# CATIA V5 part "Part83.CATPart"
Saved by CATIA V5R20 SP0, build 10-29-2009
Part number: 9FA 053012
Revision: ANY
Definition: UNKNOWN
Nomenclature: 9FA 053012
Source: Unknown
Bounding box of the stored display mesh (mm): x -2.5 to 2.5, y -6.775 to 5.225, z -2.5 to 2.5
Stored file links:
  C:\Users\Utente\Desktop\IO LAVORO\3D X SITO CF\CUMSA\3D files FA\FA 053012-20\Part83.CATPart

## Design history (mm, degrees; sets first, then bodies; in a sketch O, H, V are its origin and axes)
Set1 "FacciaKO#NONE#1477"
  DatumSurface1 "Sup1477_1"
  DatumCurve1 "Crv1477_1"
  Line1 "PCrv1477_1": stored without definition
  Line2 "PCrv1477_2": stored without definition
Set2
  DatumSurface2 "NONE"
Body1 (main body)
